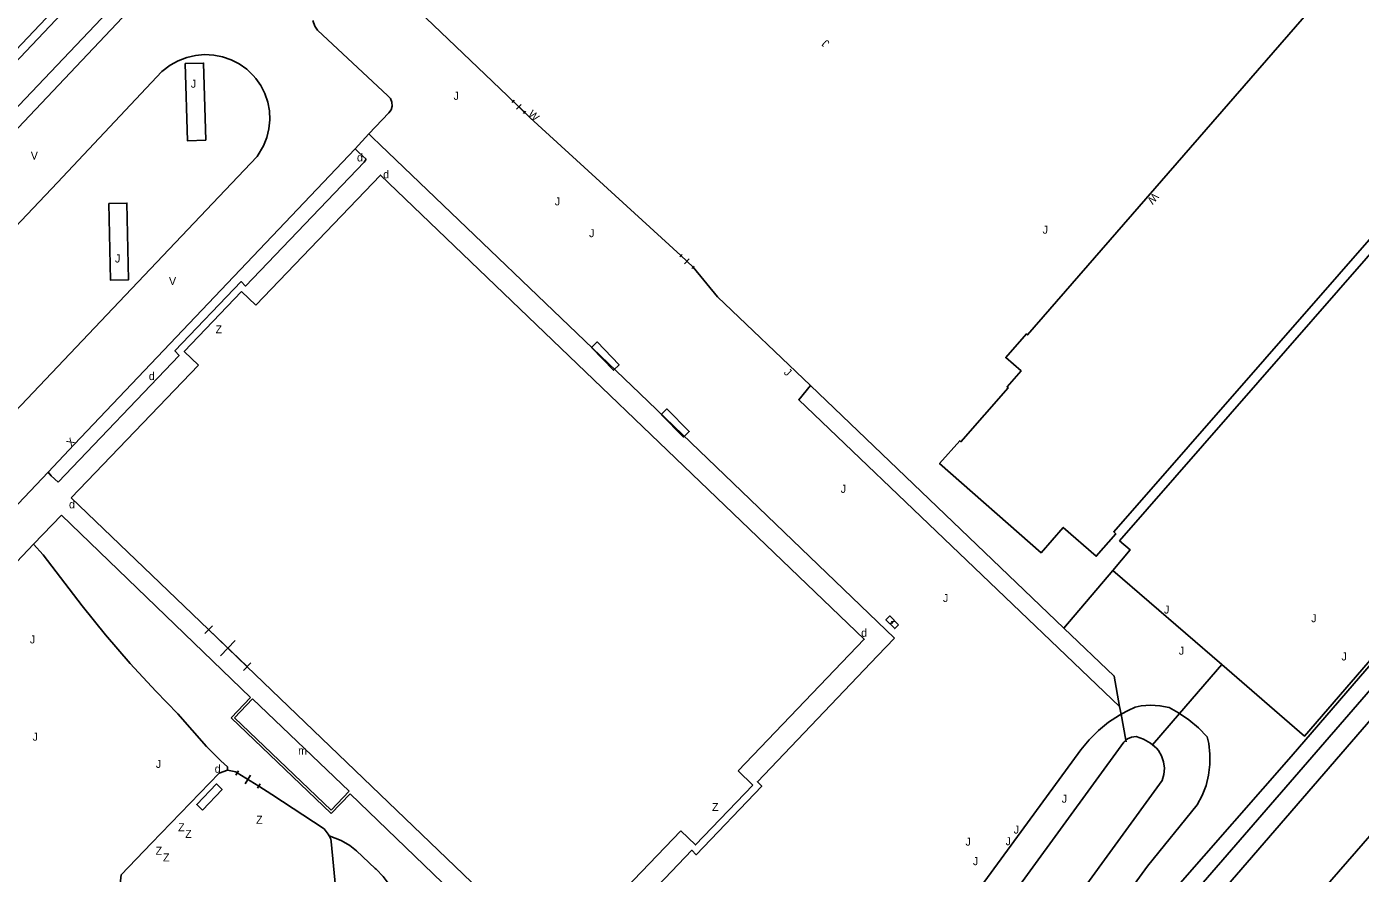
# Model space of a CAD drawing. Extents: x 134999 to 136502, y 457398 to 459002.
# Drawn here: x 135210.9 to 135294.2, y 457669.9 to 457722.8 of the extents above; entities that cross this region are included whole.
import ezdxf

# ---------------------------------------------------------------- set-up
doc = ezdxf.new("R2010")
doc.units = 0
for name, color, linetype in [('RI_DGTB_18', 7, 'Continuous'), ('RI_DGTB_29', 7, 'Continuous'), ('RI_DGTB_30', 7, 'Continuous'), ('RI_DGTB_31', 7, 'Continuous'), ('RI_DGTB_32', 7, 'Continuous'), ('RI_DGTB_4', 7, 'Continuous'), ('RI_DGTB_43', 7, 'Continuous'), ('RI_DGTB_48', 7, 'Continuous'), ('RI_DGTB_49', 7, 'Continuous'), ('RI_DGTB_53', 7, 'Continuous'), ('RI_DGTB_54', 7, 'Continuous'), ('RI_DGTB_55', 7, 'Continuous'), ('RI_DGTB_58', 7, 'Continuous'), ('RI_DGTB_6', 7, 'Continuous')]:
    doc.layers.add(name, color=color, linetype=linetype)

msp = doc.modelspace()

# ---------------------------------------------------------------- linework, layer by layer
at = {"layer": 'RI_DGTB_18'}
for points in [[(135279.238, 457679.84), (135279.675, 457680.074), (135280.126, 457680.282), (135280.5, 457680.353), (135281.086, 457680.397), (135281.672, 457680.36), (135282.247, 457680.245), (135282.837, 457679.921), (135282.891, 457679.884)], [(135282.891, 457679.884), (135283.483, 457679.481), (135284.081, 457678.978), (135284.625, 457678.416), (135284.715, 457678.005), (135284.793, 457677.347), (135284.79, 457676.685), (135284.708, 457676.028), (135284.548, 457675.386), (135284.311, 457674.767), (135284.001, 457674.182), (135280.887, 457670.34), (135275.917, 457663.501), (135266.032, 457650.232), (135261.897, 457644.646), (135250.332, 457628.456), (135245.877, 457622.542), (135242.012, 457617.331), (135224.262, 457593.174), (135222.885, 457594.053)], [(135279.238, 457679.84), (135279.14, 457679.783), (135278.459, 457679.332), (135277.824, 457678.816), (135277.244, 457678.241), (135276.722, 457677.612), (135273.385, 457673.051)], [(135273.385, 457673.051), (135266.292, 457663.355), (135260.581, 457655.457), (135255.47, 457648.257), (135249.366, 457639.74), (135243.042, 457631.228), (135239.621, 457626.587), (135237.079, 457623.091)]]:
    msp.add_lwpolyline(points, dxfattribs=at)
at = {"layer": 'RI_DGTB_29'}
for points in [[(135265.34, 457685.426), (135264.783, 457685.978), (135264.544, 457685.736), (135265.101, 457685.184), (135265.34, 457685.426)], [(135265.08, 457685.651), (135264.907, 457685.616), (135264.977, 457685.547), (135264.804, 457685.512)]]:
    msp.add_lwpolyline(points, dxfattribs=at)
at = {"layer": 'RI_DGTB_32'}
for points in [[(135246.152, 457702.741), (135247.519, 457701.315), (135247.88, 457701.661), (135246.513, 457703.087), (135246.152, 457702.741)], [(135250.507, 457698.556), (135251.909, 457697.145), (135252.263, 457697.497), (135250.862, 457698.909), (135250.507, 457698.556)], [(135221.853, 457673.853), (135223.077, 457675.136), (135222.715, 457675.481), (135221.492, 457674.198), (135221.853, 457673.853)]]:
    msp.add_lwpolyline(points, dxfattribs=at)
at = {"layer": 'RI_DGTB_4'}
msp.add_lwpolyline([(135302.891, 457718.474), (135302.467, 457718.005), (135302.295, 457718.113), (135278.78, 457691.233), (135278.907, 457691.093), (135277.688, 457689.697), (135275.624, 457691.499), (135274.242, 457689.916), (135267.906, 457695.492), (135269.162, 457696.919), (135269.235, 457696.851), (135272.195, 457700.215), (135272.12, 457700.282), (135272.992, 457701.274), (135272.039, 457702.112), (135273.325, 457703.592), (135273.401, 457703.527), (135291.543, 457724.381), (135291.468, 457724.447), (135292.61, 457725.76)], dxfattribs=at)
at = {"layer": 'RI_DGTB_43'}
msp.add_line((135229.888, 457673.635), (135231.071, 457674.873), dxfattribs=at)
at = {"layer": 'RI_DGTB_48'}
for p, q in [((135231.331, 457727.63), (135240.896, 457718.464)), ((135240.896, 457718.464), (135242.327, 457717.086)), ((135241.188, 457718.046), (135241.326, 457718.188)), ((135241.257, 457718.117), (135241.967, 457717.433)), ((135241.475, 457717.633), (135241.749, 457717.917)), ((135241.898, 457717.362), (135242.036, 457717.504)), ((135242.327, 457717.086), (135251.741, 457708.479)), ((135251.814, 457708.555), (135251.669, 457708.404)), ((135252.497, 457707.754), (135251.741, 457708.479)), ((135252.497, 457707.755), (135251.741, 457708.479)), ((135252.264, 457708.269), (135251.974, 457707.966)), ((135252.569, 457707.83), (135252.425, 457707.679)), ((135252.497, 457707.755), (135254.032, 457705.899)), ((135259.83, 457700.358), (135254.032, 457705.899)), ((135259.83, 457700.358), (135275.669, 457685.22)), ((135285.527, 457682.935), (135282.891, 457679.884)), ((135279.238, 457679.84), (135279.152, 457680.318)), ((135279.238, 457679.84), (135279.532, 457678.209)), ((135282.891, 457679.884), (135281.197, 457677.925)), ((135279.532, 457678.209), (135279.551, 457678.101)), ((135224.101, 457676.307), (135223.936, 457676.039)), ((135225.362, 457675.344), (135224.018, 457676.174)), ((135225.362, 457675.345), (135224.019, 457676.174)), ((135224.856, 457676.028), (135224.524, 457675.491)), ((135225.444, 457675.479), (135225.279, 457675.211))]:
    msp.add_line(p, q, dxfattribs=at)
for points in [[(135217.905, 457725.811), (135199.256, 457706.175), (135168.348, 457673.597), (135167.58, 457674.328)], [(135322.448, 457717.348), (135322.32, 457717.201), (135323.431, 457716.332), (135290.7, 457678.464), (135285.527, 457682.935)], [(135275.669, 457685.22), (135278.81, 457682.218), (135279.152, 457680.318)], [(135223.413, 457676.349), (135223.927, 457676.231), (135224.018, 457676.174)], [(135225.362, 457675.344), (135226.186, 457674.812), (135229.442, 457672.686)], [(135229.442, 457672.686), (135229.703, 457672.338), (135229.762, 457672.231)]]:
    msp.add_lwpolyline(points, dxfattribs=at)
at = {"layer": 'RI_DGTB_49'}
for p, q in [((135275.669, 457685.22), (135278.721, 457688.817)), ((135278.721, 457688.817), (135285.527, 457682.935))]:
    msp.add_line(p, q, dxfattribs=at)
for points in [[(135186.082, 457695.143), (135200.397, 457710.254), (135216.39, 457727.14), (135216.283, 457730.319)], [(135279.152, 457680.318), (135259.101, 457699.481), (135259.83, 457700.358)], [(135278.721, 457688.817), (135279.811, 457690.101), (135279.141, 457690.661)]]:
    msp.add_lwpolyline(points, dxfattribs=at)
at = {"layer": 'RI_DGTB_53'}
for p, q in [((135233.438, 457718.455), (135229.04, 457722.557)), ((135223.653, 457712.98), (135225.266, 457714.668)), ((135211.3, 457690.459), (135213.046, 457692.265)), ((135213.046, 457692.265), (135224.843, 457680.882)), ((135264.031, 457683.473), (135265.083, 457684.587)), ((135224.843, 457680.882), (135223.631, 457679.613)), ((135223.631, 457679.613), (135229.888, 457673.635)), ((135230.522, 457671.958), (135229.762, 457672.231)), ((135232.647, 457670.205), (135231.466, 457671.304))]:
    msp.add_line(p, q, dxfattribs=at)
for points in [[(135220.093, 457726.805), (135199.46, 457704.991), (135179.747, 457684.205), (135171.433, 457675.426)], [(135229.04, 457722.557), (135228.865, 457722.814), (135228.742, 457723.159)], [(135225.021, 457719.729), (135224.609, 457720.119), (135224.146, 457720.448), (135223.641, 457720.708), (135223.105, 457720.894), (135222.549, 457721.003), (135221.982, 457721.034), (135221.416, 457720.984), (135220.864, 457720.855), (135220.334, 457720.65), (135219.839, 457720.373), (135219.313, 457719.971)], [(135220.769, 457720.476), (135220.912, 457715.657), (135222.054, 457715.691), (135221.912, 457720.509), (135220.769, 457720.476)], [(135219.313, 457719.971), (135212.78, 457713.037), (135189.256, 457688.247), (135177.32, 457675.67)], [(135225.266, 457714.668), (135225.657, 457715.338), (135225.868, 457715.857), (135226.003, 457716.4), (135226.059, 457716.956), (135226.036, 457717.515), (135225.933, 457718.065), (135225.752, 457718.595), (135225.498, 457719.094), (135225.176, 457719.551), (135225.021, 457719.729)], [(135233.497, 457717.389), (135233.633, 457717.588), (135233.697, 457717.82), (135233.681, 457718.06), (135233.589, 457718.282), (135233.438, 457718.455)], [(135232.246, 457716.081), (135233.497, 457717.389)], [(135231.386, 457715.156), (135232.246, 457716.081)], [(135232.952, 457715.4), (135232.473, 457715.865), (135232.246, 457716.081)], [(135232.952, 457715.4), (135249.165, 457699.87), (135265.083, 457684.587)], [(135212.2, 457694.962), (135213.827, 457696.673), (135231.386, 457715.156)], [(135231.386, 457715.156), (135231.616, 457714.912), (135232.065, 457714.504)], [(135212.823, 457694.329), (135220.391, 457702.245), (135220.121, 457702.522), (135224.262, 457706.862), (135224.535, 457706.579), (135231.945, 457714.32)], [(135223.653, 457712.98), (135216.653, 457705.594), (135200.138, 457688.202), (135183.028, 457670.151)], [(135215.993, 457711.732), (135216.101, 457706.948), (135217.23, 457706.974), (135217.123, 457711.758), (135215.993, 457711.732)], [(135171.412, 457651.939), (135172.34, 457652.919), (135192.716, 457674.399), (135212.2, 457694.962)], [(135212.2, 457694.962), (135212.396, 457694.716), (135212.823, 457694.329)], [(135195.857, 457665.932), (135185.591, 457655.121), (135181.48, 457659.016), (135194.549, 457672.814), (135208.151, 457687.153), (135211.3, 457690.459)], [(135211.3, 457690.459), (135211.9, 457689.781), (135214.341, 457686.61)], [(135214.341, 457686.61), (135215.795, 457684.793), (135217.33, 457683.003), (135218.925, 457681.265), (135220.301, 457679.857)], [(135241.778, 457664.541), (135243.926, 457662.434), (135252.424, 457671.339), (135252.683, 457671.063), (135256.794, 457675.351), (135256.517, 457675.616), (135264.031, 457683.473)], [(135220.301, 457679.857), (135222.109, 457677.82), (135223.002, 457676.923)], [(135229.762, 457672.231), (135229.873, 457672.033), (135229.897, 457671.888), (135230.563, 457664.923), (135230.573, 457664.508), (135230.24, 457663.827), (135229.592, 457663.429), (135229.121, 457663.336), (135217.439, 457667.922), (135217.014, 457668.343), (135216.678, 457669.07), (135216.778, 457669.799), (135218.669, 457671.78), (135222.893, 457676.159), (135223.413, 457676.349)], [(135223.413, 457676.349), (135223.404, 457676.554), (135223.002, 457676.923)], [(135231.071, 457674.873), (135238.565, 457667.641)], [(135231.466, 457671.304), (135231.057, 457671.64), (135230.522, 457671.958)], [(135234.341, 457666.516), (135234.214, 457667.477), (135234.054, 457668.083), (135233.818, 457668.662), (135233.51, 457669.207), (135233.135, 457669.709), (135232.7, 457670.158), (135232.647, 457670.205)]]:
    msp.add_lwpolyline(points, dxfattribs=at)
at = {"layer": 'RI_DGTB_54'}
for points in [[(135225.859, 457592.087), (135229.093, 457596.234), (135237.631, 457607.935), (135241.478, 457613.178), (135245.725, 457618.923), (135249.918, 457624.708), (135250.744, 457625.814), (135259.283, 457637.533), (135261.865, 457641.002), (135264.418, 457644.492), (135267.969, 457649.188), (135273.531, 457656.651), (135279.029, 457664.161), (135281.898, 457668.107), (135282.256, 457668.535), (135282.636, 457668.944), (135289.862, 457677.192), (135297.616, 457686.163), (135307.857, 457697.893), (135319.282, 457711.138), (135323.758, 457716.133)], [(135324.42, 457715.48), (135311.855, 457700.931), (135297.939, 457684.983), (135283.559, 457668.38), (135282.566, 457667.276), (135279.957, 457663.705)], [(135325.395, 457714.7), (135312.345, 457699.589), (135298.429, 457683.641), (135284.049, 457667.038), (135283.056, 457665.934), (135276.706, 457657.242), (135270.861, 457649.099), (135263.416, 457638.885), (135260.839, 457635.407), (135251.887, 457623.111), (135247.499, 457617.047), (135241.313, 457608.66)], [(135231.817, 457587.839), (135240.607, 457599.736), (135247.755, 457609.38), (135250.141, 457612.706), (135257.778, 457623.177), (135262.982, 457630.275), (135267.289, 457636.273), (135273.154, 457644.368), (135275.511, 457647.533), (135286.065, 457661.986), (135287.341, 457663.633), (135288.68, 457665.23), (135289.334, 457665.967), (135302.48, 457681.093), (135316.344, 457696.917), (135323.753, 457705.451), (135329.021, 457711.551)]]:
    msp.add_lwpolyline(points, dxfattribs=at)
at = {"layer": 'RI_DGTB_55'}
for p, q in [((135231.945, 457714.32), (135232.065, 457714.504)), ((135222.464, 457685.362), (135222.001, 457684.882)), ((135224.627, 457682.809), (135222.225, 457685.123)), ((135224.636, 457682.808), (135222.233, 457685.122)), ((135223.897, 457684.446), (135222.972, 457683.485)), ((135224.867, 457683.048), (135224.404, 457682.568))]:
    msp.add_line(p, q, dxfattribs=at)
for points in [[(135185.47, 457695.271), (135215.862, 457727.337), (135215.786, 457730.099), (135197.645, 457747.306), (135159.802, 457783.181), (135142.09, 457800)], [(135279.141, 457690.661), (135303.201, 457718.191), (135302.891, 457718.474)], [(135225.181, 457705.376), (135232.978, 457713.504), (135263.198, 457684.516), (135255.311, 457676.293)], [(135224.285, 457706.231), (135220.706, 457702.48), (135221.592, 457701.634)], [(135225.181, 457705.376), (135224.285, 457706.231)], [(135213.642, 457693.347), (135221.592, 457701.634)], [(135222.225, 457685.123), (135213.642, 457693.347)], [(135251.728, 457672.558), (135243.862, 457664.358), (135224.627, 457682.809)], [(135255.311, 457676.293), (135256.234, 457675.41)], [(135256.234, 457675.41), (135252.656, 457671.671), (135251.728, 457672.558)]]:
    msp.add_lwpolyline(points, dxfattribs=at)
at = {"layer": 'RI_DGTB_58'}
for points in [[(135222.614, 457594.247), (135241.084, 457619.454), (135254.653, 457637.898), (135257.854, 457642.555), (135259.661, 457644.995), (135261.406, 457647.428), (135263.803, 457650.71), (135265.618, 457653.462), (135273.837, 457664.732), (135281.809, 457675.701), (135281.917, 457676.08), (135281.947, 457676.473), (135281.897, 457676.863), (135281.769, 457677.236), (135281.569, 457677.575), (135281.459, 457677.712), (135281.197, 457677.925)], [(135238.111, 457622.191), (135255.058, 457644.561), (135260.188, 457651.761), (135263.264, 457655.89), (135265.351, 457658.882), (135271.674, 457667.46), (135279.405, 457678.082), (135279.532, 457678.209)], [(135281.197, 457677.925), (135281.078, 457678.022), (135280.652, 457678.267), (135280.181, 457678.442), (135279.901, 457678.404), (135279.642, 457678.289), (135279.532, 457678.209)]]:
    msp.add_lwpolyline(points, dxfattribs=at)
at = {"layer": 'RI_DGTB_6'}
for p, q in [((135224.973, 457680.801), (135223.843, 457679.618)), ((135231.013, 457675.03), (135224.973, 457680.801)), ((135223.843, 457679.618), (135229.883, 457673.847)), ((135229.883, 457673.847), (135231.013, 457675.03))]:
    msp.add_line(p, q, dxfattribs=at)

# ---------------------------------------------------------------- texts
at = {"layer": 'RI_DGTB_29'}
for p in [(135231.501, 457714.362), (135233.139, 457713.306), (135218.494, 457700.705), (135213.508, 457692.693), (135263, 457684.673), (135222.61, 457676.181)]:
    msp.add_text('d', height=0.5, dxfattribs=at).set_placement(p)
at = {"layer": 'RI_DGTB_30'}
for s, height, rotation, p in [('W', 0.499, 316.64569, (135242.146, 457717.258)), ('W', 0.5, 228.65529, (135281.262, 457712.445)), ('X', 0.5, 46.44604, (135213.655, 457696.492))]:
    msp.add_text(s, height=height, rotation=rotation, dxfattribs=at).set_placement(p)
for p in [(135211.119, 457714.476), (135219.756, 457706.64)]:
    msp.add_text('V', height=0.5, dxfattribs=at).set_placement(p)
at = {"layer": 'RI_DGTB_31'}
for height, rotation, p in [(0.5, 138.82109, (135261.064, 457721.798)), (0.5, 359.99973, (135274.339, 457709.848)), (0.499, 316.64569, (135258.13, 457701.137)), (0.5, 359.99973, (135281.921, 457686.122)), (0.5, 359.99973, (135291.121, 457685.582)), (0.5, 359.99973, (135282.851, 457683.552)), (0.5, 359.99973, (135293.011, 457683.192))]:
    msp.add_text('J', height=height, rotation=rotation, dxfattribs=at).set_placement(p)
for p in [(135221.121, 457718.965), (135237.536, 457718.211), (135243.858, 457711.617), (135246.002, 457709.631), (135216.381, 457708.049), (135261.724, 457693.664), (135268.111, 457686.845), (135211.066, 457684.258), (135211.234, 457678.182), (135218.934, 457676.484), (135275.53, 457674.308), (135269.521, 457671.627), (135272.025, 457671.656), (135272.532, 457672.38), (135269.985, 457670.408)]:
    msp.add_text('J', height=0.5, dxfattribs=at).set_placement(p)
at = {"layer": 'RI_DGTB_32'}
for p in [(135222.663, 457703.624), (135253.682, 457673.79), (135220.327, 457672.526), (135225.201, 457672.996), (135220.768, 457672.114), (135218.921, 457671.059), (135219.381, 457670.641)]:
    msp.add_text('Z', height=0.5, dxfattribs=at).set_placement(p)
at = {"layer": 'RI_DGTB_43'}
msp.add_text('m', height=0.5, dxfattribs=at).set_placement((135227.823, 457677.317))

doc.saveas('drawing.dxf')
